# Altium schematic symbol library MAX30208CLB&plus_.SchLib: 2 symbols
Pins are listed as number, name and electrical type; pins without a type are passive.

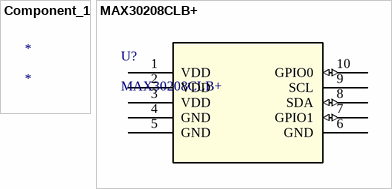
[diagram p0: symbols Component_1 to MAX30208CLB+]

## Component_1
designator *

## MAX30208CLB+
designator U?
No Description Available; Vendor: Maxim Integrated Products; Built_By: EMA_Rebekah; SourceLibrary: Maxim_2019-09-13
footprint 21-100265_MXM
pins: 1 VDD (power), 2 VDD (power), 3 VDD (power), 4 GND, 5 GND, 6 GND, 7 GPIO1 (io), 8 SDA (io), 9 SCL, 10 GPIO0 (io)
